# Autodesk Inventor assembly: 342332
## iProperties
Company: Mayer & Müller AG Schaltgeräte
Created: 2006-01
Part Number: 342332
Document SubType Name: Assembly
Designer: I.Baliuc
Manufacturer: Standard
Standards Organization: Custom
Description: Spule
Mass: 769.163 g
Surface Area: 1205.53 cm^2
Volume: 87.1497 cm^3
Density: 8.82576 g/cm^3
Zweck: für Blasspule
Author: T.Messerschmitt
Revision Number: 342332
